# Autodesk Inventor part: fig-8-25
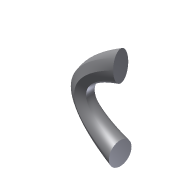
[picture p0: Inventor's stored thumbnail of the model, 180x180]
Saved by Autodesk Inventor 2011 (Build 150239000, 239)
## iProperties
Created: 2008-06
Part Number: fig-8-25
Document SubType Name: Modeling
Designer: CADCIM
Density: 1 g/cm^3
Author: CADCIM
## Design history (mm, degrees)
sketch "Sketch1"
  geometry: L1 (-0.077, 5.773)-(4.961, 2.953); L2 (4.961, 2.953)-(5.038, -2.82); L3 (5.038, -2.82)-(0.077, -5.773); L4 (0.077, -5.773)-(-4.961, -2.953); L5 (-4.961, -2.953)-(-5.038, 2.82); L6 (-5.038, 2.82)-(-0.077, 5.773); 1 further point
  constraints: 12 end point, 13 other
  dimensions: "d0" = 10 distance between parallel lines of L2 L5
workplane "Work Plane1"
sketch "Sketch2"
  geometry: C1 r 7.5 at (-0.159, -25); 1 further point
  constraints: 1 centre point
  dimensions: "d2" = 15 diameter of C1; "d3" = 25 vertical distance of C1.centre point (0, 0)
sketch "Sketch3" dims "d4" = 10, "d5" = 5
  geometry: 2 further points; 1 other entity
  constraints: 2 other
  dimensions: "d6" = 25 vertical distance of point (0.175, 25) point (0, 0)
loft "Loft1" sketch "Sketch2", "Sketch3" dims "d7" = 0, "d8" = 90 deg, "d9" = 0, "d10" = 90 deg, "d11" = 0, "d12" = 90 deg
body "Solid1"
other parameters: "d1" = 25
